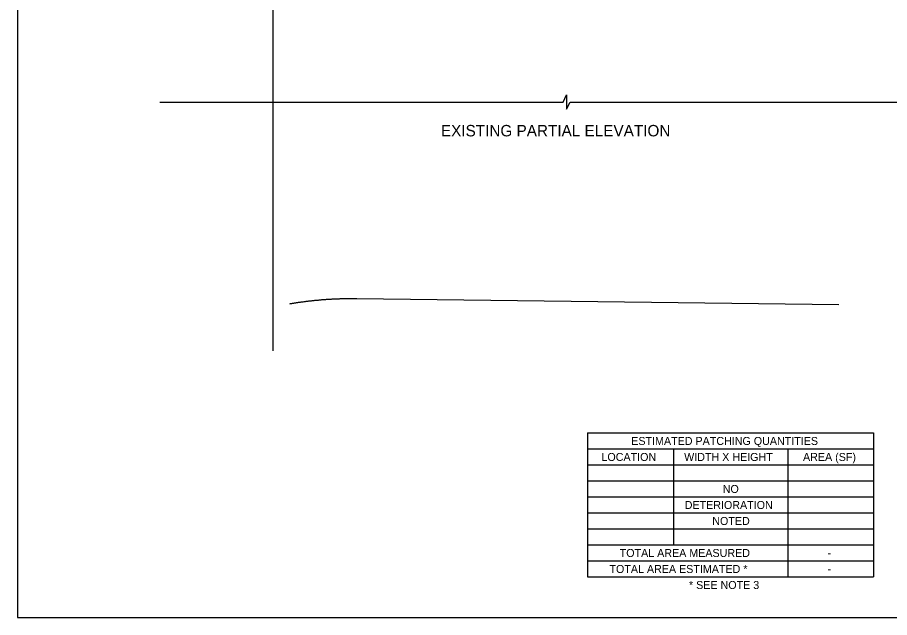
# Model space of a CAD drawing. Extents: x 100 to 130.5, y 100 to 121.
# Drawn here: x 100 to 115.25, y 100 to 110.5 of the extents above; entities that cross this region are included whole.
import ezdxf

# ---------------------------------------------------------------- set-up
doc = ezdxf.new("R2010")
doc.units = 0
for name, color, linetype in [('BR_P_Gen_Text', 7, 'Continuous'), ('Default', 7, 'Continuous'), ('SC_Scratch1', 7, 'Continuous')]:
    doc.layers.add(name, color=color, linetype=linetype)

msp = doc.modelspace()

# ---------------------------------------------------------------- linework, layer by layer
at = {"layer": 'BR_P_Gen_Text'}
for p, q in [((104.468, 120.5), (104.468, 104.668)), ((109.54, 109.019), (109.602, 109.144)), ((109.602, 109.144), (109.602, 108.894)), ((102.489, 109.019), (109.54, 109.019)), ((109.602, 108.894), (109.665, 109.019)), ((109.665, 109.019), (115.946, 109.019)), ((109.97, 103.23), (109.97, 100.71)), ((109.97, 103.23), (114.97, 103.23)), ((114.97, 103.23), (114.97, 100.71)), ((109.97, 102.95), (114.97, 102.95)), ((111.47, 102.95), (111.47, 101.27)), ((113.47, 102.95), (113.47, 100.71)), ((109.97, 102.67), (114.97, 102.67)), ((109.97, 102.39), (114.97, 102.39)), ((109.97, 102.11), (114.97, 102.11)), ((109.97, 101.83), (114.97, 101.83)), ((109.97, 101.55), (114.97, 101.55)), ((109.97, 101.27), (114.97, 101.27)), ((109.97, 100.99), (114.97, 100.99)), ((109.97, 100.71), (114.97, 100.71))]:
    msp.add_line(p, q, dxfattribs=at)
at = {"layer": 'Default'}
msp.add_line((105.935, 105.583), (114.364, 105.478), dxfattribs=at)
msp.add_spline([(104.762, 105.491), (104.785, 105.495), (104.809, 105.499), (104.832, 105.503), (104.856, 105.507), (104.88, 105.51), (104.904, 105.514), (104.928, 105.517), (104.952, 105.521), (104.975, 105.524), (104.999, 105.527), (105.023, 105.53), (105.047, 105.533), (105.071, 105.536), (105.095, 105.539), (105.119, 105.542), (105.143, 105.544), (105.166, 105.547), (105.19, 105.55), (105.214, 105.552), (105.238, 105.554), (105.262, 105.556), (105.286, 105.559), (105.31, 105.561), (105.334, 105.563), (105.358, 105.564), (105.382, 105.566), (105.406, 105.568), (105.43, 105.569), (105.454, 105.571), (105.478, 105.572), (105.502, 105.574), (105.526, 105.575), (105.55, 105.576), (105.574, 105.577), (105.598, 105.578), (105.622, 105.579), (105.646, 105.58), (105.67, 105.581), (105.694, 105.581), (105.718, 105.582), (105.742, 105.582), (105.767, 105.583), (105.791, 105.583), (105.815, 105.583), (105.839, 105.583), (105.863, 105.583), (105.887, 105.583), (105.911, 105.583), (105.935, 105.583)], degree=3, dxfattribs=at)
at = {"layer": 'SC_Scratch1'}
msp.add_lwpolyline([(100, 100), (130.5, 100), (130.5, 121), (100, 121)], close=True, dxfattribs=at)

# ---------------------------------------------------------------- texts
at = {"layer": 'BR_P_Gen_Text'}
for s, height, p in [('EXISTING PARTIAL ELEVATION', 0.2, (107.405, 108.419)), ('ESTIMATED PATCHING QUANTITIES', 0.14, (110.733, 103.02)), ('LOCATION', 0.14, (110.212, 102.74)), ('WIDTH X HEIGHT', 0.14, (111.658, 102.74)), ('AREA (SF)', 0.14, (113.737, 102.74)), ('NO', 0.14, (112.333, 102.18)), ('DETERIORATION', 0.14, (111.668, 101.9)), ('NOTED', 0.14, (112.15, 101.62)), ('TOTAL AREA MEASURED', 0.14, (110.531, 101.06)), ('-', 0.14, (114.167, 101.06)), ('TOTAL AREA ESTIMATED *', 0.14, (110.352, 100.78)), ('-', 0.14, (114.167, 100.78)), ('* SEE NOTE 3', 0.14, (111.743, 100.5))]:
    msp.add_text(s, height=height, dxfattribs=at).set_placement(p)

doc.saveas('drawing.dxf')
